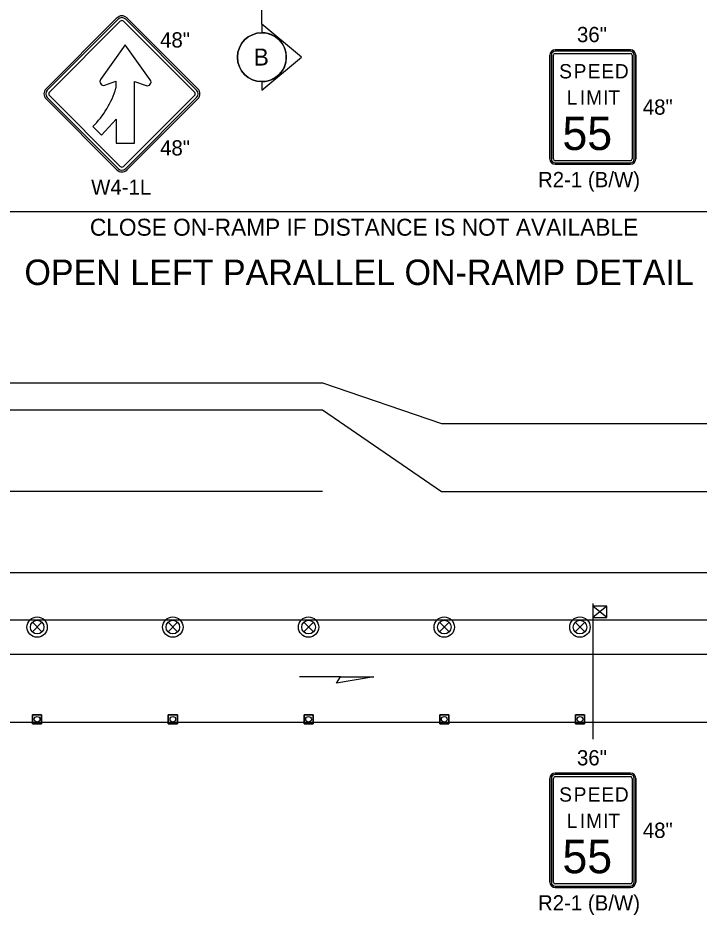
# Model space of a CAD drawing. Extents: x 99999 to 100116, y 99995 to 100013.
# Drawn here: x 100070.739 to 100073.951, y 100002.24 to 100006.47 of the extents above; entities that cross this region are included whole.
import ezdxf

# ---------------------------------------------------------------- set-up
doc = ezdxf.new("R2010")
doc.units = 0
for name, color, linetype in [('Default', 7, 'Continuous'), ('RD_MK_LineEdgeYellow', 7, 'Continuous'), ('RD_MK_LineLane', 7, 'Continuous'), ('SH_DE_DetailHeading2Text', 7, 'Continuous'), ('SH_GI_SectionCut', 7, 'Continuous'), ('TR_SN_ConstructionSigns', 7, 'Continuous'), ('TR_WZ_PortableSignMount5ftMinBlk-Wht', 7, 'Continuous'), ('TR_WZ_TrafficCone', 7, 'Continuous'), ('TR_WZ_TrafficSafetyDrum', 7, 'Continuous'), ('TR_WZ_WorkZoneDetails', 7, 'Continuous'), ('TR_WZ_WorkZoneTextCurrent', 7, 'Continuous')]:
    doc.layers.add(name, color=color, linetype=linetype)

msp = doc.modelspace()

# ---------------------------------------------------------------- linework, layer by layer
at = {"layer": 'Default'}
for p, q in [((100071.2055, 100006.4701), (100070.8714, 100006.136)), ((100071.5873, 100006.136), (100071.2532, 100006.4701)), ((100070.8714, 100006.0883), (100071.2055, 100005.7542)), ((100071.2532, 100005.7542), (100071.5873, 100006.0883))]:
    msp.add_line(p, q, dxfattribs=at)
for centre, start, end in [((100071.2294, 100006.4463), 45, 135), ((100070.8953, 100006.1122), 135, 225), ((100071.5635, 100006.1122), 315, 45), ((100071.2294, 100005.7781), 225, 315)]:
    msp.add_arc(centre, 0.0338, start, end, dxfattribs=at)
at = {"layer": 'RD_MK_LineEdgeYellow'}
for p, q in [((100070.6655, 100004.622), (100072.1758, 100004.622)), ((100072.1758, 100004.622), (100072.7368, 100004.238)), ((100072.7368, 100004.238), (100075.43, 100004.238)), ((100068.195, 100003.47), (100075.43, 100003.47))]:
    msp.add_line(p, q, dxfattribs=at)
at = {"layer": 'RD_MK_LineLane'}
for points in [[(100072.1758, 100004.238), (100070.6024, 100004.238)], [(100075.43, 100003.854), (100068.195, 100003.854)]]:
    msp.add_lwpolyline(points, dxfattribs=at)
at = {"layer": 'SH_GI_SectionCut'}
for p, q in [((100071.8894, 100006.441), (100071.8894, 100007.8761)), ((100071.8894, 100006.441), (100071.8894, 100006.4003)), ((100072.0755, 100006.2851), (100071.8894, 100006.441)), ((100071.8894, 100006.1292), (100072.0755, 100006.2851)), ((100071.8894, 100006.1699), (100071.8894, 100006.1292))]:
    msp.add_line(p, q, dxfattribs=at)
msp.add_circle((100071.8894, 100006.2851), 0.1152, dxfattribs=at)
msp.add_circle((100071.8894, 100006.2851), 0.1152, dxfattribs=at)
for start, end in [(90.0022, 269.9978), (269.9978, 90.0022), (269.9978, 90.0022)]:
    msp.add_arc((100071.8894, 100006.2851), 0.1152, start, end, dxfattribs=at)
at = {"layer": 'TR_SN_ConstructionSigns'}
for p, q in [((100070.8714, 100006.136), (100071.2055, 100006.4701)), ((100071.2115, 100006.4642), (100070.8774, 100006.1301)), ((100070.8873, 100006.1201), (100071.2214, 100006.4542)), ((100071.2373, 100006.4542), (100071.5714, 100006.1201)), ((100071.5814, 100006.1301), (100071.2473, 100006.4642)), ((100071.2532, 100006.4701), (100071.5873, 100006.136)), ((100071.2453, 100006.3441), (100071.1288, 100006.1802)), ((100071.3632, 100006.1784), (100071.2453, 100006.3441)), ((100073.2728, 100006.32), (100073.6272, 100006.32)), ((100073.6272, 100006.32), (100073.2728, 100006.32)), ((100073.2475, 100005.8053), (100073.2475, 100006.2947)), ((100073.2475, 100006.2947), (100073.2475, 100005.8053)), ((100073.2546, 100006.2947), (100073.2546, 100005.8053)), ((100073.2644, 100005.8053), (100073.2644, 100006.2947)), ((100073.6272, 100006.313), (100073.2728, 100006.313)), ((100073.2728, 100006.3032), (100073.6272, 100006.3032)), ((100073.6357, 100006.2947), (100073.6357, 100005.8053)), ((100073.6455, 100005.8053), (100073.6455, 100006.2947)), ((100073.6525, 100006.2947), (100073.6525, 100005.8053)), ((100073.6525, 100005.8053), (100073.6525, 100006.2947)), ((100071.1493, 100006.1532), (100071.2012, 100006.1718)), ((100071.2012, 100006.1718), (100071.2012, 100006.1394)), ((100071.288, 100005.8802), (100071.288, 100006.1703)), ((100071.288, 100006.1703), (100071.3429, 100006.1513)), ((100071.2055, 100005.7542), (100070.8714, 100006.0883)), ((100070.8774, 100006.0943), (100071.2115, 100005.7602)), ((100071.2214, 100005.7701), (100070.8873, 100006.1042)), ((100071.5714, 100006.1042), (100071.2373, 100005.7701)), ((100071.2473, 100005.7602), (100071.5814, 100006.0943)), ((100071.5873, 100006.0883), (100071.2532, 100005.7542)), ((100071.1335, 100005.9171), (100071.2027, 100005.9936)), ((100071.2027, 100005.9936), (100071.2027, 100005.8802)), ((100071.0923, 100005.9583), (100071.1335, 100005.9171)), ((100071.2027, 100005.8802), (100071.288, 100005.8802)), ((100073.6272, 100005.7969), (100073.2728, 100005.7969)), ((100073.2728, 100005.7871), (100073.6272, 100005.7871)), ((100073.6272, 100005.78), (100073.2728, 100005.78)), ((100073.2728, 100005.78), (100073.6272, 100005.78)), ((100073.2728, 100002.91), (100073.6272, 100002.91)), ((100073.6272, 100002.91), (100073.2728, 100002.91)), ((100073.6272, 100002.9029), (100073.2728, 100002.9029)), ((100073.2475, 100002.3953), (100073.2475, 100002.8846)), ((100073.2475, 100002.8846), (100073.2475, 100002.3953)), ((100073.2546, 100002.8846), (100073.2546, 100002.3953)), ((100073.2644, 100002.3953), (100073.2644, 100002.8846)), ((100073.2728, 100002.8931), (100073.6272, 100002.8931)), ((100073.6357, 100002.8846), (100073.6357, 100002.3953)), ((100073.6455, 100002.3953), (100073.6455, 100002.8846)), ((100073.6525, 100002.8846), (100073.6525, 100002.3953)), ((100073.6525, 100002.3953), (100073.6525, 100002.8846)), ((100073.6272, 100002.3868), (100073.2728, 100002.3868)), ((100073.2728, 100002.377), (100073.6272, 100002.377)), ((100073.6272, 100002.37), (100073.2728, 100002.37)), ((100073.2728, 100002.37), (100073.6272, 100002.37))]:
    msp.add_line(p, q, dxfattribs=at)
for centre, radius, start, end in [((100071.2294, 100006.4463), 0.0338, 45, 135), ((100071.2294, 100006.4463), 0.0253, 45, 135), ((100071.2294, 100006.4463), 0.0113, 45, 135), ((100073.2728, 100006.2947), 0.0253, 90, 180), ((100073.2728, 100006.2947), 0.0253, 90, 180), ((100073.6272, 100006.2947), 0.0253, 360, 90), ((100073.6272, 100006.2947), 0.0253, 360, 90), ((100073.2728, 100006.2947), 0.0183, 90, 180), ((100073.2728, 100006.2947), 0.00844, 90, 180), ((100073.6272, 100006.2947), 0.0183, 0, 90), ((100073.6272, 100006.2947), 0.00844, 360, 90), ((100071.1433, 100006.17), 0.0177, 144.5862, 289.6669), ((100071.3487, 100006.1681), 0.0177, 250.8938, 35.4138), ((100070.8953, 100006.1122), 0.0338, 135, 225), ((100070.8953, 100006.1122), 0.0253, 135, 225), ((100070.8953, 100006.1122), 0.0113, 135, 225), ((100070.7881, 100006.2645), 0.4316, 314.815, 343.157), ((100071.5635, 100006.1122), 0.0113, 315, 45), ((100071.5635, 100006.1122), 0.0253, 315, 45), ((100071.5635, 100006.1122), 0.0338, 315, 45), ((100073.2728, 100005.8053), 0.0253, 180, 270), ((100073.2728, 100005.8053), 0.0253, 180, 270), ((100073.2728, 100005.8053), 0.0183, 180, 270), ((100073.2728, 100005.8053), 0.00844, 180, 270), ((100073.6272, 100005.8053), 0.0253, 270, 360), ((100073.6272, 100005.8053), 0.0183, 270, 360), ((100073.6272, 100005.8053), 0.00844, 270, 0), ((100073.6272, 100005.8053), 0.0253, 270, 360), ((100071.2294, 100005.7781), 0.0338, 225, 315), ((100071.2294, 100005.7781), 0.0253, 225, 315), ((100071.2294, 100005.7781), 0.0113, 225, 315), ((100073.2728, 100002.8846), 0.0253, 90, 180), ((100073.2728, 100002.8846), 0.0253, 90, 180), ((100073.2728, 100002.8846), 0.0183, 90, 180), ((100073.6272, 100002.8846), 0.0253, 360, 90), ((100073.6272, 100002.8846), 0.0253, 360, 90), ((100073.6272, 100002.8846), 0.0183, 0, 90), ((100073.2728, 100002.8846), 0.00844, 90, 180), ((100073.6272, 100002.8846), 0.00844, 360, 90), ((100073.2728, 100002.3953), 0.0253, 180, 270), ((100073.2728, 100002.3953), 0.0253, 180, 270), ((100073.2728, 100002.3953), 0.0183, 180, 270), ((100073.2728, 100002.3953), 0.00844, 180, 270), ((100073.6272, 100002.3953), 0.0253, 270, 360), ((100073.6272, 100002.3953), 0.0183, 270, 360), ((100073.6272, 100002.3953), 0.00844, 270, 0), ((100073.6272, 100002.3953), 0.0253, 270, 360)]:
    msp.add_arc(centre, radius, start, end, dxfattribs=at)
at = {"layer": 'TR_WZ_PortableSignMount5ftMinBlk-Wht'}
for p, q in [((100073.45, 100003.71), (100073.45, 100003.63)), ((100073.5167, 100003.644), (100073.45, 100003.696)), ((100073.5167, 100003.696), (100073.45, 100003.644)), ((100073.4834, 100003.67), (100073.4834, 100003.67)), ((100073.4835, 100003.6699), (100073.4835, 100003.6699))]:
    msp.add_line(p, q, dxfattribs=at)
msp.add_lwpolyline([(100073.5167, 100003.644), (100073.5167, 100003.696), (100073.45, 100003.696), (100073.45, 100003.644)], close=True, dxfattribs=at)
at = {"layer": 'TR_WZ_TrafficCone'}
for points in [[(100070.8081, 100003.142), (100070.8507, 100003.142), (100070.8507, 100003.1846), (100070.8081, 100003.1846), (100070.8081, 100003.142)], [(100070.8081, 100003.1846), (100070.8507, 100003.1846), (100070.8507, 100003.142), (100070.8081, 100003.142), (100070.8081, 100003.1846)], [(100071.4481, 100003.142), (100071.4907, 100003.142), (100071.4907, 100003.1846), (100071.4481, 100003.1846), (100071.4481, 100003.142)], [(100071.4481, 100003.1846), (100071.4907, 100003.1846), (100071.4907, 100003.142), (100071.4481, 100003.142), (100071.4481, 100003.1846)], [(100072.0881, 100003.142), (100072.1307, 100003.142), (100072.1307, 100003.1846), (100072.0881, 100003.1846), (100072.0881, 100003.142)], [(100072.0881, 100003.1846), (100072.1307, 100003.1846), (100072.1307, 100003.142), (100072.0881, 100003.142), (100072.0881, 100003.1846)], [(100072.7281, 100003.142), (100072.7707, 100003.142), (100072.7707, 100003.1846), (100072.7281, 100003.1846), (100072.7281, 100003.142)], [(100072.7281, 100003.1846), (100072.7707, 100003.1846), (100072.7707, 100003.142), (100072.7281, 100003.142), (100072.7281, 100003.1846)], [(100073.3681, 100003.142), (100073.4107, 100003.142), (100073.4107, 100003.1846), (100073.3681, 100003.1846), (100073.3681, 100003.142)], [(100073.3681, 100003.1846), (100073.4107, 100003.1846), (100073.4107, 100003.142), (100073.3681, 100003.142), (100073.3681, 100003.1846)]]:
    msp.add_lwpolyline(points, dxfattribs=at)
for centre in [(100070.8294, 100003.1633), (100071.4694, 100003.1633), (100072.1094, 100003.1633), (100072.7494, 100003.1633), (100073.3894, 100003.1633)]:
    msp.add_circle(centre, 0.0133, dxfattribs=at)
at = {"layer": 'TR_WZ_TrafficSafetyDrum'}
for p, q in [((100070.8068, 100003.5753), (100070.852, 100003.6206)), ((100070.852, 100003.5753), (100070.8068, 100003.6206)), ((100071.4468, 100003.5753), (100071.492, 100003.6206)), ((100071.492, 100003.5753), (100071.4468, 100003.6206)), ((100072.0868, 100003.5753), (100072.132, 100003.6206)), ((100072.132, 100003.5753), (100072.0868, 100003.6206)), ((100072.7268, 100003.5753), (100072.772, 100003.6206)), ((100072.772, 100003.5753), (100072.7268, 100003.6206)), ((100073.3668, 100003.5753), (100073.412, 100003.6206)), ((100073.412, 100003.5753), (100073.3668, 100003.6206))]:
    msp.add_line(p, q, dxfattribs=at)
for centre, radius in [((100070.8294, 100003.598), 0.048), ((100070.8294, 100003.598), 0.048), ((100070.8294, 100003.598), 0.032), ((100071.4694, 100003.598), 0.048), ((100071.4694, 100003.598), 0.048), ((100071.4694, 100003.598), 0.032), ((100072.1094, 100003.598), 0.048), ((100072.1094, 100003.598), 0.048), ((100072.1094, 100003.598), 0.032), ((100072.7494, 100003.598), 0.048), ((100072.7494, 100003.598), 0.048), ((100072.7494, 100003.598), 0.032), ((100073.3894, 100003.598), 0.048), ((100073.3894, 100003.598), 0.048), ((100073.3894, 100003.598), 0.032)]:
    msp.add_circle(centre, radius, dxfattribs=at)
at = {"layer": 'TR_WZ_WorkZoneDetails'}
for p, q in [((100074.4628, 100005.5563), (100070.6024, 100005.5563)), ((100070.6703, 100004.75), (100072.1758, 100004.75)), ((100072.1758, 100004.75), (100072.7368, 100004.558)), ((100072.7368, 100004.558), (100075.43, 100004.558)), ((100073.45, 100003.63), (100073.45, 100003.07)), ((100072.2594, 100003.3639), (100072.0665, 100003.3639)), ((100068.195, 100003.15), (100075.43, 100003.15))]:
    msp.add_line(p, q, dxfattribs=at)
for points in [[(100068.275, 100003.63), (100068.275, 100004.558), (100069.2533, 100004.558), (100068.275, 100004.8881), (100068.275, 100004.8881), (100068.275, 100004.8881), (100068.275, 100005.5642), (100068.275, 100005.5642), (100068.275, 100005.5642), (100069.2641, 100005.228), (100070.6703, 100004.75), (100072.1758, 100004.75), (100072.7368, 100004.558), (100075.35, 100004.558), (100075.35, 100003.63)], [(100072.4166, 100003.3639), (100072.2415, 100003.333), (100072.2594, 100003.3639)]]:
    msp.add_lwpolyline(points, close=True, dxfattribs=at)

# ---------------------------------------------------------------- texts
at = {"layer": 'Default'}
for s, height, p in [('S', 0.0675, (100073.2914, 100006.185)), ('P', 0.0675, (100073.3596, 100006.185)), ('E', 0.0675, (100073.4257, 100006.185)), ('E', 0.0675, (100073.4899, 100006.185)), ('D', 0.0675, (100073.554, 100006.185)), ('L', 0.0675, (100073.3265, 100006.0613)), ('I', 0.0675, (100073.3886, 100006.0613)), ('M', 0.0675, (100073.4183, 100006.0613)), ('I', 0.0675, (100073.4993, 100006.0613)), ('T', 0.0675, (100073.5229, 100006.0613)), ('55', 0.1575, (100073.3068, 100005.8475))]:
    msp.add_text(s, height=height, dxfattribs=at).set_placement(p)
for s, height, p in [('S', 0.0675, (100073.2914, 100002.775)), ('P', 0.0675, (100073.3596, 100002.775)), ('E', 0.0675, (100073.4257, 100002.775)), ('E', 0.0675, (100073.4899, 100002.775)), ('D', 0.0675, (100073.554, 100002.775)), ('L', 0.0675, (100073.3265, 100002.6512)), ('I', 0.0675, (100073.3886, 100002.6512)), ('M', 0.0675, (100073.4183, 100002.6512)), ('I', 0.0675, (100073.4993, 100002.6512)), ('T', 0.0675, (100073.5229, 100002.6512)), ('55', 0.1575, (100073.3068, 100002.4375))]:
    msp.add_text(s, height=height, rotation=360, dxfattribs=at).set_placement(p)
at = {"layer": 'SH_DE_DetailHeading2Text'}
msp.add_text('OPEN LEFT PARALLEL ON-RAMP DETAIL', height=0.12, rotation=360, dxfattribs=at).set_placement((100070.7694, 100005.211))
at = {"layer": 'SH_GI_SectionCut'}
msp.add_text('B', height=0.08, rotation=359.99, dxfattribs=at).set_placement((100071.8507, 100006.2458))
at = {"layer": 'TR_SN_ConstructionSigns'}
msp.add_text('36"', height=0.072, dxfattribs=at).set_placement((100073.3753, 100006.356))
for s, p in [('48"', (100071.4092, 100006.3307)), ('48"', (100071.4092, 100005.8216)), ('W4-1L', (100071.084, 100005.6363)), ('36"', (100073.3753, 100002.946))]:
    msp.add_text(s, height=0.072, rotation=360, dxfattribs=at).set_placement(p)
at = {"layer": 'TR_WZ_WorkZoneDetails'}
for s, p in [('48"', (100073.6858, 100006.014)), ('R2-1 (B/W)', (100073.1913, 100005.672))]:
    msp.add_text(s, height=0.072, dxfattribs=at).set_placement(p)
for s, p in [('48"', (100073.6858, 100002.604)), ('R2-1 (B/W)', (100073.1913, 100002.262))]:
    msp.add_text(s, height=0.072, rotation=360, dxfattribs=at).set_placement(p)
at = {"layer": 'TR_WZ_WorkZoneTextCurrent'}
msp.add_text('CLOSE ON-RAMP IF DISTANCE IS NOT AVAILABLE', height=0.08, dxfattribs=at).set_placement((100071.0782, 100005.4434))

doc.saveas('drawing.dxf')
